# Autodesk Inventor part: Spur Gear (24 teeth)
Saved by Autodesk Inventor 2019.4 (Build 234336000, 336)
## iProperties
Created: 2020-02
Part Number: Spur Gear (24 teeth)
Material: Generic
Description: Spur Gear; Module: 1.0; Num Teeth: 24; Pressure Angle: 20.0; Backlash: 0.00 mm
Document SubType Name: Modeling
Designer: Administrator
Density: 1 g/cm^3
Appearance: Default
Title: Spur Gear (24 teeth)
Author: Administrator
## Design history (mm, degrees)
